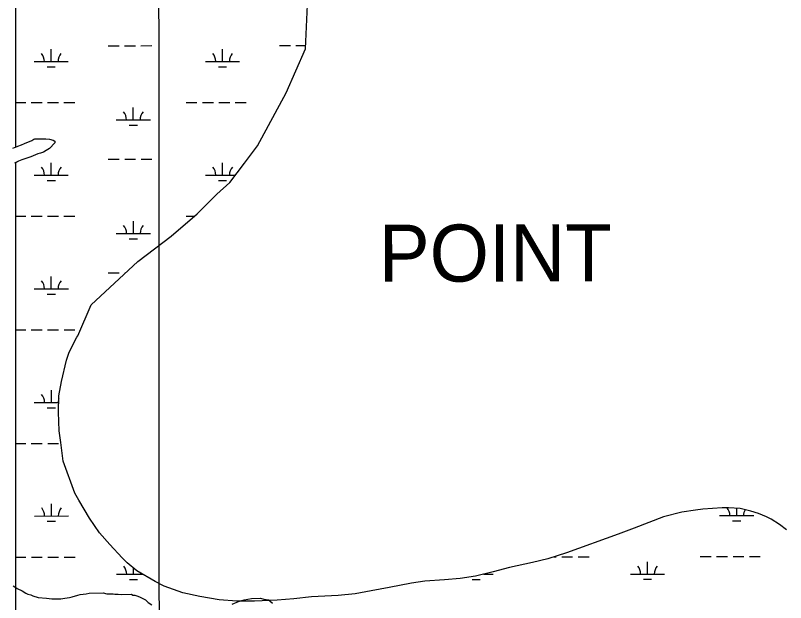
# Model space of a CAD drawing. Extents: x 3279314 to 3317160, y 734079 to 759431.
# Drawn here: x 3301399 to 3303655, y 742915 to 744634 of the extents above; entities that cross this region are included whole.
import ezdxf

# ---------------------------------------------------------------- set-up
doc = ezdxf.new("R2010")
doc.units = 0
for name, color, linetype in [('V-GRID-MAJR', 7, 'Continuous'), ('V-SITE-VEGE', 7, 'Continuous'), ('V-TOPO-GNAM-IDEN', 7, 'Continuous'), ('V-WETL-SWMP', 7, 'Continuous')]:
    doc.layers.add(name, color=color, linetype=linetype)

msp = doc.modelspace()

# ---------------------------------------------------------------- linework, layer by layer
at = {"layer": 'V-GRID-MAJR'}
msp.add_spline([(3301822.6, 739465.2), (3301819.1, 745523.7), (3301815.6, 751585.5), (3301812, 757647.4), (3301812, 757650.7)], degree=3, dxfattribs=at)
at = {"layer": 'V-SITE-VEGE'}
for points in [[(3301391.7, 744245.4), (3301406.2, 744251.7), (3301416.6, 744255.9), (3301426, 744259.1), (3301446.8, 744268.6), (3301453, 744271.8), (3301456.1, 744272.8), (3301488.4, 744273), (3301498.9, 744272), (3301509.3, 744268.9), (3301514.5, 744265.8), (3301514.6, 744261.6), (3301499, 744244.9), (3301488.6, 744238.6), (3301481.3, 744234.4), (3301472, 744231.2), (3301464.7, 744229.1), (3301457.4, 744225.9), (3301443.9, 744220.6), (3301417.9, 744211.1), (3301407.5, 744208), (3301396, 744201.7)], [(3301392.6, 742963.7), (3301399.9, 742959.5), (3301404.1, 742956.4), (3301418.7, 742949.2), (3301429.2, 742943), (3301435.4, 742939.9), (3301443.8, 742937.9), (3301450.1, 742934.8), (3301465.7, 742929.6), (3301489.7, 742927.7), (3301505.3, 742925.7), (3301532.4, 742925.8), (3301543.9, 742927.9), (3301557.4, 742930.1), (3301564.7, 742932.2), (3301581.3, 742936.4), (3301588.6, 742938.6), (3301606.3, 742940.7), (3301614.7, 742942.9), (3301656.3, 742943.1), (3301666.8, 742941), (3301685.5, 742941.1), (3301689.7, 742940.1), (3301700.1, 742940.1), (3301709.5, 742939.1), (3301738.7, 742939.3), (3301742.9, 742937.2), (3301749.1, 742937.2), (3301757.5, 742934.2), (3301764.8, 742931.1), (3301780.4, 742922.8), (3301787.8, 742915.5), (3301798.2, 742908.3)], [(3302033.7, 742910.5), (3302052.4, 742917.9), (3302069.1, 742923.1), (3302091, 742927.4), (3302117, 742927.5), (3302126.4, 742925.5), (3302140, 742923.5), (3302144.1, 742920.4), (3302152.5, 742913.1)]]:
    msp.add_lwpolyline(points, dxfattribs=at)
at = {"layer": 'V-WETL-SWMP'}
for p, q in [((3301398.9, 745828.8), (3301398.9, 744248.5)), ((3301398.9, 745828.8), (3301398.9, 744248.5)), ((3302249, 744536.5), (3302260.7, 744789.3)), ((3302249, 744536.5), (3302260.7, 744789.3)), ((3301670.8, 744545.8), (3301702.8, 744545.8)), ((3301718.8, 744545.8), (3301750.8, 744545.8)), ((3301766.8, 744545.8), (3301798.8, 744545.9)), ((3302172.7, 744546), (3302204.7, 744546.1)), ((3302220.7, 744546.1), (3302249.5, 744546.1)), ((3301503.7, 744499.3), (3301503.7, 744535.3)), ((3302005.7, 744499.5), (3302005.6, 744535.5)), ((3302192, 744408.1), (3302249, 744536.5)), ((3302192, 744408.1), (3302249, 744536.5)), ((3301453.7, 744499.2), (3301553.7, 744499.3)), ((3301955.7, 744499.5), (3302055.7, 744499.6)), ((3301491.8, 744483.8), (3301515.8, 744483.8)), ((3301993.7, 744484.1), (3302017.7, 744484.1)), ((3302108.1, 744252.6), (3302192, 744408.1)), ((3302108.1, 744252.6), (3302192, 744408.1)), ((3301398.9, 744379.1), (3301429, 744379.2)), ((3301445, 744379.2), (3301477, 744379.2)), ((3301493, 744379.2), (3301525, 744379.2)), ((3301541, 744379.2), (3301573, 744379.2)), ((3301744.3, 744328.6), (3301744.3, 744364.6)), ((3301898.9, 744379.4), (3301930.9, 744379.4)), ((3301946.9, 744379.4), (3301978.9, 744379.4)), ((3301994.9, 744379.4), (3302026.9, 744379.5)), ((3302042.9, 744379.5), (3302074.9, 744379.5)), ((3301694.3, 744328.6), (3301794.3, 744328.6)), ((3301732.3, 744313.1), (3301756.3, 744313.2)), ((3301426, 744259.1), (3301446.8, 744268.6)), ((3301426, 744259.1), (3301446.8, 744268.6)), ((3301446.8, 744268.6), (3301453, 744271.8)), ((3301446.8, 744268.6), (3301453, 744271.8)), ((3301453, 744271.8), (3301456.1, 744272.8)), ((3301453, 744271.8), (3301456.1, 744272.8)), ((3301456.1, 744272.8), (3301488.5, 744273)), ((3301456.1, 744272.8), (3301488.5, 744273)), ((3301488.5, 744273), (3301498.9, 744272)), ((3301488.5, 744273), (3301498.9, 744272)), ((3301498.9, 744272), (3301509.3, 744268.9)), ((3301498.9, 744272), (3301509.3, 744268.9)), ((3301509.3, 744268.9), (3301514.5, 744265.8)), ((3301509.3, 744268.9), (3301514.5, 744265.8)), ((3301398.9, 744248.5), (3301406.2, 744251.7)), ((3301398.9, 744248.5), (3301406.2, 744251.7)), ((3301406.2, 744251.7), (3301416.6, 744255.9)), ((3301406.2, 744251.7), (3301416.6, 744255.9)), ((3301416.6, 744255.9), (3301426, 744259.1)), ((3301416.6, 744255.9), (3301426, 744259.1)), ((3301514.6, 744261.6), (3301499, 744244.9)), ((3301514.6, 744261.6), (3301499, 744244.9)), ((3301514.5, 744265.8), (3301514.6, 744261.6)), ((3301514.5, 744265.8), (3301514.6, 744261.6)), ((3302069.6, 744201.8), (3302108.1, 744252.6)), ((3302069.6, 744201.8), (3302108.1, 744252.6)), ((3301457.4, 744225.9), (3301443.9, 744220.7)), ((3301457.4, 744225.9), (3301443.9, 744220.7)), ((3301464.7, 744229.1), (3301457.4, 744225.9)), ((3301464.7, 744229.1), (3301457.4, 744225.9)), ((3301472, 744231.2), (3301464.7, 744229.1)), ((3301472, 744231.2), (3301464.7, 744229.1)), ((3301481.3, 744234.4), (3301472, 744231.2)), ((3301481.3, 744234.4), (3301472, 744231.2)), ((3301488.6, 744238.6), (3301481.3, 744234.4)), ((3301488.6, 744238.6), (3301481.3, 744234.4)), ((3301499, 744244.9), (3301488.6, 744238.6)), ((3301499, 744244.9), (3301488.6, 744238.6)), ((3301407.5, 744208), (3301398.9, 744203.2)), ((3301407.5, 744208), (3301398.9, 744203.2)), ((3301398.9, 744203.2), (3301398.9, 739465)), ((3301398.9, 744203.2), (3301398.9, 739465)), ((3301417.9, 744211.1), (3301407.5, 744208)), ((3301417.9, 744211.1), (3301407.5, 744208)), ((3301443.9, 744220.7), (3301417.9, 744211.1)), ((3301443.9, 744220.7), (3301417.9, 744211.1)), ((3301503.9, 744166.6), (3301503.9, 744202.6)), ((3301671, 744213.1), (3301703, 744213.1)), ((3301719, 744213.1), (3301751, 744213.2)), ((3301767, 744213.2), (3301799, 744213.2)), ((3302005.8, 744166.9), (3302005.8, 744202.9)), ((3302027.5, 744145.2), (3302069.6, 744201.8)), ((3302027.5, 744145.2), (3302069.6, 744201.8)), ((3301453.9, 744166.6), (3301553.9, 744166.6)), ((3301955.8, 744166.8), (3302043.6, 744166.9)), ((3301491.9, 744151.2), (3301515.9, 744151.2)), ((3301988.9, 744110.9), (3302027.5, 744145.2)), ((3301988.9, 744110.9), (3302027.5, 744145.2)), ((3301993.8, 744151.4), (3302017.8, 744151.4)), ((3301931.6, 744053.1), (3301988.9, 744110.9)), ((3301931.6, 744053.1), (3301988.9, 744110.9)), ((3301398.9, 744046.5), (3301429.1, 744046.5)), ((3301445.1, 744046.5), (3301477.1, 744046.5)), ((3301493.1, 744046.5), (3301525.1, 744046.5)), ((3301541.1, 744046.5), (3301573.1, 744046.6)), ((3301855.5, 743988.1), (3301931.6, 744053.1)), ((3301855.5, 743988.1), (3301931.6, 744053.1)), ((3301899, 744046.7), (3301924.2, 744046.7)), ((3301744.5, 743995.9), (3301744.5, 744031.9)), ((3301694.5, 743995.9), (3301794.5, 743995.9)), ((3301732.5, 743980.5), (3301756.5, 743980.5)), ((3301757.1, 743913.5), (3301855.5, 743988.1)), ((3301757.1, 743913.5), (3301855.5, 743988.1)), ((3301620.8, 743787.4), (3301757.1, 743913.5)), ((3301620.8, 743787.4), (3301757.1, 743913.5)), ((3301504.1, 743833.9), (3301504.1, 743869.9)), ((3301671.1, 743880.4), (3301703.1, 743880.5)), ((3301719.1, 743880.5), (3301721.4, 743880.5)), ((3301454.1, 743833.9), (3301554.1, 743833.9)), ((3301492.1, 743818.5), (3301516.1, 743818.5)), ((3301581.5, 743696), (3301620.8, 743787.4)), ((3301581.5, 743696), (3301620.8, 743787.4)), ((3301398.9, 743713.8), (3301429.3, 743713.8)), ((3301445.3, 743713.8), (3301477.3, 743713.8)), ((3301493.3, 743713.8), (3301525.3, 743713.9)), ((3301541.3, 743713.9), (3301573.3, 743713.9)), ((3301556.4, 743648.3), (3301579.2, 743692)), ((3301556.4, 743648.3), (3301579.2, 743692)), ((3301579.2, 743692), (3301581.5, 743696)), ((3301579.2, 743692), (3301581.5, 743696)), ((3301548.6, 743625.2), (3301556.4, 743648.3)), ((3301548.6, 743625.2), (3301556.4, 743648.3)), ((3301533.8, 743562.5), (3301548.6, 743625.2)), ((3301533.8, 743562.5), (3301548.6, 743625.2)), ((3301526.1, 743520.4), (3301533.8, 743562.5)), ((3301526.1, 743520.4), (3301533.8, 743562.5)), ((3301504.3, 743501.2), (3301504.2, 743537.2)), ((3301454.3, 743501.2), (3301525.5, 743501.3)), ((3301524.7, 743472.8), (3301526.1, 743520.4)), ((3301524.7, 743472.8), (3301526.1, 743520.4)), ((3301492.3, 743485.8), (3301516.3, 743485.8)), ((3301527.3, 743418.1), (3301524.7, 743472.8)), ((3301527.3, 743418.1), (3301524.7, 743472.8)), ((3301531.5, 743384), (3301527.3, 743418.1)), ((3301531.5, 743384), (3301527.3, 743418.1)), ((3301398.9, 743381.1), (3301429.5, 743381.1)), ((3301445.5, 743381.1), (3301477.5, 743381.2)), ((3301493.5, 743381.2), (3301525.5, 743381.2)), ((3301538.9, 743329.3), (3301531.5, 743384)), ((3301538.9, 743329.3), (3301531.5, 743384)), ((3301572.7, 743235.1), (3301538.9, 743329.3)), ((3301572.7, 743235.1), (3301538.9, 743329.3)), ((3301584.6, 743214.5), (3301572.7, 743235.1)), ((3301584.6, 743214.5), (3301572.7, 743235.1)), ((3301615.8, 743162.3), (3301584.6, 743214.5)), ((3301615.8, 743162.3), (3301584.6, 743214.5)), ((3301504.4, 743168.6), (3301504.4, 743204.6)), ((3303391.8, 743185.9), (3303351.3, 743180.1)), ((3303391.8, 743185.9), (3303351.3, 743180.1)), ((3303413.2, 743188.4), (3303391.8, 743185.9)), ((3303413.2, 743188.4), (3303391.8, 743185.9)), ((3303469.5, 743192.6), (3303413.2, 743188.4)), ((3303469.5, 743192.6), (3303413.2, 743188.4)), ((3303487.7, 743192.7), (3303469.5, 743192.6)), ((3303487.7, 743192.7), (3303469.5, 743192.6)), ((3303522.6, 743190.5), (3303487.7, 743192.7)), ((3303522.6, 743190.5), (3303487.7, 743192.7)), ((3303512.1, 743169.6), (3303512, 743191.2)), ((3303553.6, 743182.7), (3303522.6, 743190.5)), ((3303553.6, 743182.7), (3303522.6, 743190.5)), ((3301454.4, 743168.5), (3301554.4, 743168.6)), ((3303297.5, 743166.4), (3303211.2, 743132.7)), ((3303297.5, 743166.4), (3303211.2, 743132.7)), ((3303351.3, 743180.1), (3303297.5, 743166.4)), ((3303351.3, 743180.1), (3303297.5, 743166.4)), ((3303462.1, 743169.6), (3303562.1, 743169.6)), ((3303575.9, 743175.7), (3303553.6, 743182.7)), ((3303575.9, 743175.7), (3303553.6, 743182.7)), ((3303598.9, 743166.3), (3303575.9, 743175.7)), ((3303598.9, 743166.3), (3303575.9, 743175.7)), ((3303613.2, 743159.2), (3303598.9, 743166.3)), ((3303613.2, 743159.2), (3303598.9, 743166.3)), ((3301492.4, 743153.1), (3301516.4, 743153.1)), ((3301645.4, 743118.8), (3301615.8, 743162.3)), ((3301645.4, 743118.8), (3301615.8, 743162.3)), ((3303500.1, 743154.2), (3303524.1, 743154.2)), ((3303637.9, 743143.4), (3303613.2, 743159.2)), ((3303637.9, 743143.4), (3303613.2, 743159.2)), ((3303657.8, 743128.5), (3303637.9, 743143.4)), ((3303657.8, 743128.5), (3303637.9, 743143.4)), ((3301675.7, 743084.9), (3301645.4, 743118.8)), ((3301675.7, 743084.9), (3301645.4, 743118.8)), ((3303211.2, 743132.7), (3303165.2, 743115)), ((3303211.2, 743132.7), (3303165.2, 743115)), ((3303165.2, 743115), (3303013.2, 743060.3)), ((3303165.2, 743115), (3303013.2, 743060.3)), ((3301711.6, 743046.2), (3301675.7, 743084.9)), ((3301711.6, 743046.2), (3301675.7, 743084.9)), ((3303013.2, 743060.3), (3302958.6, 743043.4)), ((3303013.2, 743060.3), (3302958.6, 743043.4)), ((3301398.9, 743048.4), (3301429.6, 743048.5)), ((3301445.6, 743048.5), (3301477.6, 743048.5)), ((3301493.6, 743048.5), (3301525.6, 743048.5)), ((3301541.6, 743048.5), (3301573.6, 743048.5)), ((3301726.7, 743031.2), (3301711.6, 743046.2)), ((3301726.7, 743031.2), (3301711.6, 743046.2)), ((3301754.6, 743008.3), (3301726.7, 743031.2)), ((3301754.6, 743008.3), (3301726.7, 743031.2)), ((3302913.4, 743032.1), (3302846, 743017.5)), ((3302913.4, 743032.1), (3302846, 743017.5)), ((3302958.6, 743043.4), (3302913.4, 743032.1)), ((3302958.6, 743043.4), (3302913.4, 743032.1)), ((3302977.4, 743049.2), (3302983.4, 743049.3)), ((3302999.4, 743049.3), (3303031.4, 743049.3)), ((3303047.4, 743049.3), (3303079.4, 743049.3)), ((3303250.7, 742998.6), (3303250.7, 743034.6)), ((3303405.3, 743049.5), (3303437.3, 743049.5)), ((3303453.3, 743049.5), (3303485.3, 743049.5)), ((3303501.3, 743049.5), (3303533.3, 743049.5)), ((3303549.3, 743049.5), (3303581.3, 743049.6)), ((3301745, 742997.9), (3301745, 743016.2)), ((3301807.9, 742976.8), (3301754.6, 743008.3)), ((3301807.9, 742976.8), (3301754.6, 743008.3)), ((3302798.5, 743005.4), (3302747, 742992.4)), ((3302798.5, 743005.4), (3302747, 742992.4)), ((3302846, 743017.5), (3302798.5, 743005.4)), ((3302846, 743017.5), (3302798.5, 743005.4)), ((3301695, 742997.9), (3301772.2, 742997.9)), ((3301733, 742982.4), (3301757, 742982.5)), ((3302701.8, 742985.1), (3302655.8, 742981.7)), ((3302701.8, 742985.1), (3302655.8, 742981.7)), ((3302747, 742992.4), (3302701.8, 742985.1)), ((3302747, 742992.4), (3302701.8, 742985.1)), ((3302736.8, 742983), (3302760.8, 742983)), ((3302770.8, 742998.4), (3302798.8, 742998.4)), ((3303200.7, 742998.6), (3303300.7, 742998.7)), ((3303238.7, 742983.2), (3303262.7, 742983.2)), ((3301834.9, 742963.5), (3301807.9, 742976.8)), ((3301834.9, 742963.5), (3301807.9, 742976.8)), ((3301889.8, 742943.9), (3301834.9, 742963.5)), ((3301889.8, 742943.9), (3301834.9, 742963.5)), ((3302559.1, 742971.7), (3302494.1, 742959.5)), ((3302559.1, 742971.7), (3302494.1, 742959.5)), ((3302598.7, 742977.4), (3302559.1, 742971.7)), ((3302598.7, 742977.4), (3302559.1, 742971.7)), ((3302655.8, 742981.7), (3302598.7, 742977.4)), ((3302655.8, 742981.7), (3302598.7, 742977.4)), ((3301939, 742933), (3301889.8, 742943.9)), ((3301939, 742933), (3301889.8, 742943.9)), ((3302394.3, 742940.8), (3302344.3, 742935.8)), ((3302394.3, 742940.8), (3302344.3, 742935.8)), ((3302441, 742949.7), (3302394.3, 742940.8)), ((3302441, 742949.7), (3302394.3, 742940.8)), ((3302494.1, 742959.5), (3302441, 742949.7)), ((3302494.1, 742959.5), (3302441, 742949.7)), ((3301996.2, 742923), (3301939, 742933)), ((3301996.2, 742923), (3301939, 742933)), ((3302047.7, 742919.3), (3301996.2, 742923)), ((3302047.7, 742919.3), (3301996.2, 742923)), ((3302099.3, 742919.5), (3302047.7, 742919.3)), ((3302099.3, 742919.5), (3302047.7, 742919.3)), ((3302165.9, 742922.2), (3302099.3, 742919.5)), ((3302165.9, 742922.2), (3302099.3, 742919.5)), ((3302214.3, 742926.4), (3302165.9, 742922.2)), ((3302214.3, 742926.4), (3302165.9, 742922.2)), ((3302266.6, 742931.4), (3302214.3, 742926.4)), ((3302266.6, 742931.4), (3302214.3, 742926.4)), ((3302344.3, 742935.8), (3302266.6, 742931.4)), ((3302344.3, 742935.8), (3302266.6, 742931.4))]:
    msp.add_line(p, q, dxfattribs=at)
for centre, start, end in [((3301448.5, 744499.7), 359.2573, 40.801), ((3301559, 744499.8), 139.2573, 180.801), ((3301950.4, 744500), 359.2573, 40.801), ((3302060.9, 744500), 139.2573, 180.801), ((3301689.1, 744329), 359.2573, 40.801), ((3301799.5, 744329.1), 139.2573, 180.801), ((3301448.7, 744167), 359.2573, 40.801), ((3301559.2, 744167.1), 139.2573, 180.801), ((3301950.6, 744167.3), 359.2573, 40.801), ((3302061.1, 744167.4), 139.2573, 180.801), ((3301689.2, 743996.4), 359.2573, 40.801), ((3301799.7, 743996.4), 139.2573, 180.801), ((3301448.8, 743834.4), 359.2573, 40.801), ((3301559.3, 743834.4), 139.2573, 180.801), ((3301449, 743501.7), 359.2573, 40.801), ((3301559.5, 743501.7), 162.8018, 180.801), ((3301449.2, 743169), 359.2573, 40.801), ((3301559.7, 743169.1), 139.2573, 180.801), ((3303456.8, 743170), 359.2573, 39.9697), ((3303567.3, 743170.1), 151.281, 180.801), ((3301689.7, 742998.3), 359.2573, 40.801), ((3303195.5, 742999.1), 359.2573, 40.801), ((3303305.9, 742999.1), 139.2573, 180.801), ((3301800.2, 742998.4), 174.0269, 180.801)]:
    msp.add_arc(centre, 35.2, start, end, dxfattribs=at)

# ---------------------------------------------------------------- texts
at = {"layer": 'V-TOPO-GNAM-IDEN'}
msp.add_text('POINT', height=167, rotation=0.1349, dxfattribs=at).set_placement((3302463.8, 743854.4))

doc.saveas('drawing.dxf')
